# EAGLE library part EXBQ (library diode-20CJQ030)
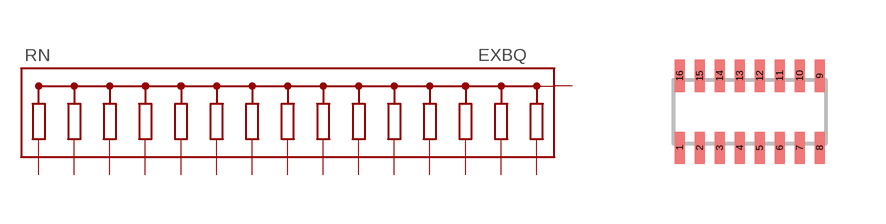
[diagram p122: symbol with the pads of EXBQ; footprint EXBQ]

Designator prefix RN

## EXBQ  [EXBQ]
1  1  pas
2  2  pas
3  3  pas
4  4  pas
5  5  pas
6  6  pas
7  7  pas
8  8  pas
9  9  pas
10  10  pas
11  11  pas
12  12  pas
13  13  pas
14  14  pas
15  15  pas
16  POL  pas

## Footprint EXBQ (pad centres in mm)
Panasonic EXBQ:1506 Chip Resistor Networks
smd 0.25 x 0.8: 1 -1.75,-0.9; 2 -1.25,-0.9; 3 -0.75,-0.9; 4 -0.25,-0.9; 5 0.25,-0.9; 6 0.75,-0.9; 7 1.25,-0.9; 8 1.75,-0.9; 9 1.75,0.9; 10 1.25,0.9; 11 0.75,0.9; 12 0.25,0.9; 13 -0.25,0.9; 14 -0.75,0.9; 15 -1.25,0.9; 16 -1.75,0.9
